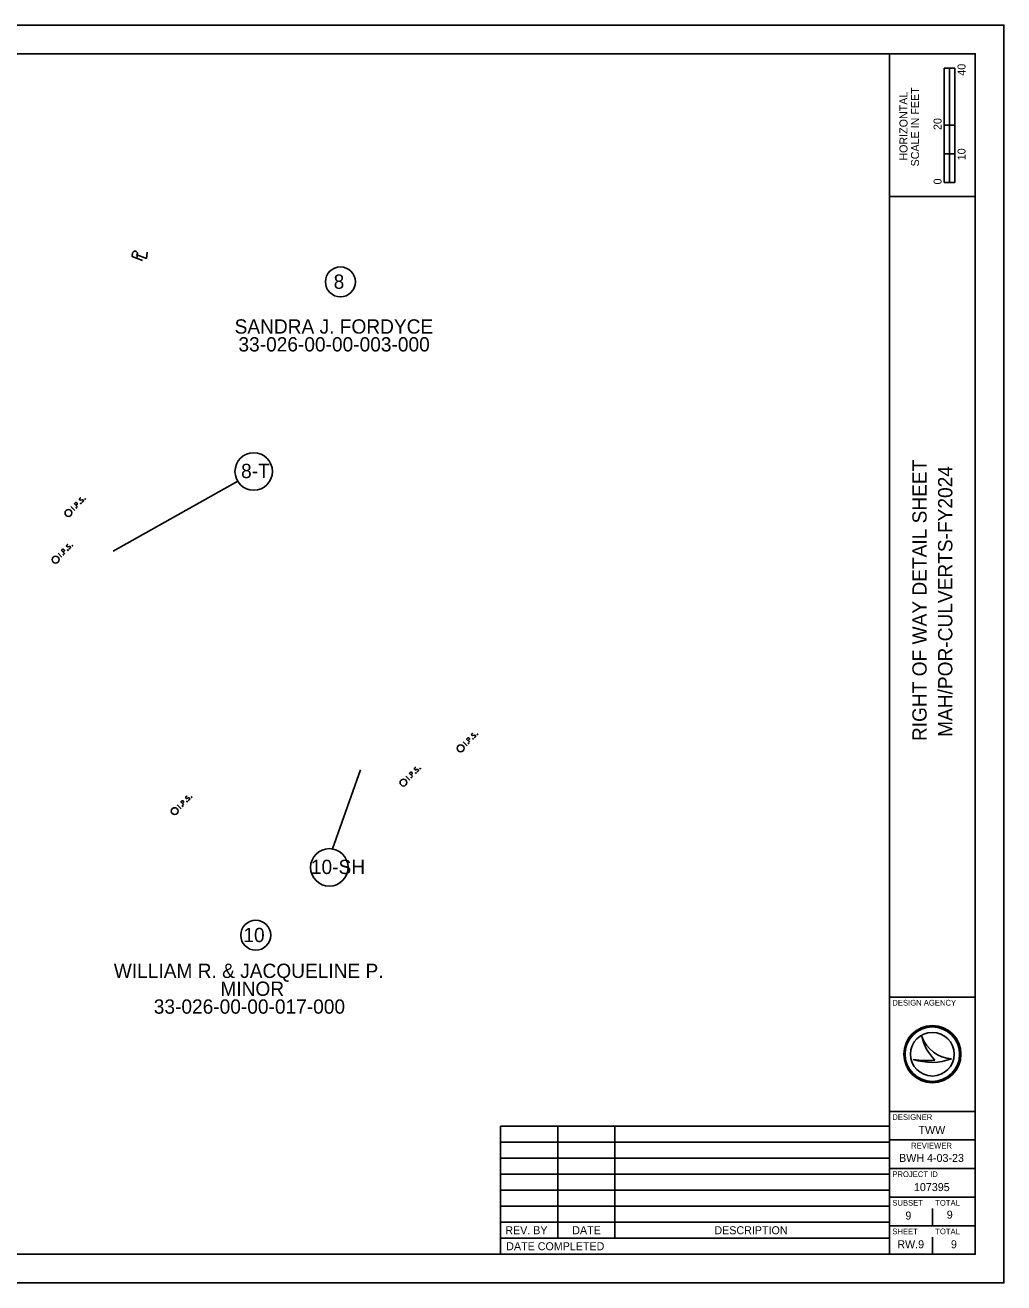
# Model space of a CAD drawing. Extents: x -0.2 to 34, y 0 to 22.
# Drawn here: x 16.88 to 34, y 0 to 22 of the extents above; entities that cross this region are included whole.
import ezdxf

# ---------------------------------------------------------------- set-up
doc = ezdxf.new("R2010")
doc.units = 0
for name, color, linetype in [('DR_X_Culvert', 7, 'Continuous'), ('DR_X_Elev_Flow', 7, 'Continuous'), ('RD_X_GR_Lt', 7, 'Continuous'), ('SH_Border', 7, 'Continuous'), ('SH_Cut_Line', 7, 'Continuous'), ('SH_Data', 7, 'Continuous'), ('SV_X_Random_Point', 7, 'Continuous'), ('UT_X_Unknown_Cells', 7, 'Continuous')]:
    doc.layers.add(name, color=color, linetype=linetype)

msp = doc.modelspace()

# ---------------------------------------------------------------- linework, layer by layer
at = {"layer": 'DR_X_Culvert'}
for p, q in [((18.839, 17.92), (18.848, 18.001)), ((18.884, 17.966), (18.884, 17.966))]:
    msp.add_line(p, q, dxfattribs=at)
for points in [[(18.935, 17.883), (18.757, 17.952), (18.764, 18.016)], [(18.826, 17.989), (19.004, 17.919), (19.016, 18.028)]]:
    msp.add_lwpolyline(points, dxfattribs=at)
msp.add_arc((18.805, 18.005), 0.0431, 354.2311, 165.0883, dxfattribs=at)
at = {"layer": 'DR_X_Elev_Flow'}
for p, q in [((20.602, 14.021), (18.422, 12.797)), ((22.261, 7.59), (22.751, 8.975)), ((25.197, 2.74), (25.197, 0.5)), ((25.197, 2.74), (32, 2.74)), ((26.197, 2.74), (26.197, 0.78)), ((27.197, 2.74), (27.197, 0.78)), ((25.197, 2.46), (32, 2.46)), ((25.197, 2.18), (32, 2.18)), ((25.197, 1.9), (32, 1.9)), ((25.197, 1.62), (32, 1.62)), ((25.197, 1.34), (32, 1.34)), ((25.197, 1.06), (32, 1.06)), ((25.197, 0.78), (32, 0.78)), ((32, 0.5), (32, 0.5))]:
    msp.add_line(p, q, dxfattribs=at)
for centre in [(20.881, 14.193), (22.203, 7.267)]:
    msp.add_circle(centre, 0.328, dxfattribs=at)
at = {"layer": 'RD_X_GR_Lt'}
for points in [[(17.802, 13.571), (17.746, 13.628), (17.764, 13.647), (17.767, 13.648), (17.77, 13.65), (17.772, 13.65), (17.774, 13.651), (17.778, 13.65), (17.782, 13.649), (17.786, 13.646), (17.791, 13.641), (17.793, 13.639), (17.795, 13.635), (17.796, 13.631), (17.796, 13.628), (17.796, 13.626), (17.795, 13.623), (17.792, 13.619), (17.773, 13.6)], [(17.856, 13.73), (17.854, 13.731), (17.852, 13.73), (17.847, 13.728), (17.842, 13.725), (17.839, 13.722), (17.838, 13.72), (17.834, 13.714), (17.833, 13.707), (17.833, 13.701), (17.836, 13.696), (17.839, 13.694), (17.843, 13.691), (17.849, 13.691), (17.884, 13.699), (17.888, 13.699), (17.891, 13.698), (17.894, 13.696), (17.897, 13.694), (17.899, 13.691), (17.9, 13.688), (17.902, 13.685), (17.903, 13.683), (17.903, 13.681), (17.904, 13.678), (17.903, 13.676), (17.903, 13.674), (17.902, 13.672), (17.899, 13.668), (17.893, 13.663), (17.889, 13.66), (17.881, 13.658), (17.875, 13.658)], [(17.93, 13.714), (17.932, 13.716), (17.934, 13.717), (17.937, 13.716), (17.939, 13.714), (17.94, 13.711), (17.939, 13.709), (17.937, 13.707), (17.935, 13.706), (17.932, 13.707), (17.93, 13.709), (17.93, 13.712), (17.93, 13.714)], [(17.684, 13.566), (17.696, 13.579)], [(17.747, 13.516), (17.69, 13.573)], [(17.741, 13.51), (17.753, 13.522)], [(17.773, 13.558), (17.775, 13.56), (17.777, 13.56), (17.78, 13.559), (17.782, 13.557), (17.783, 13.554), (17.783, 13.552), (17.781, 13.55), (17.779, 13.55), (17.776, 13.55), (17.774, 13.553), (17.773, 13.556), (17.773, 13.558)], [(17.853, 13.637), (17.855, 13.639), (17.857, 13.639), (17.86, 13.639), (17.862, 13.637), (17.862, 13.634), (17.862, 13.632), (17.86, 13.63), (17.858, 13.629), (17.855, 13.63), (17.853, 13.632), (17.852, 13.635), (17.853, 13.637)], [(17.459, 12.75), (17.471, 12.763)], [(17.577, 12.755), (17.52, 12.812), (17.539, 12.831), (17.541, 12.832), (17.545, 12.834), (17.547, 12.834), (17.549, 12.835), (17.553, 12.834), (17.556, 12.833), (17.561, 12.83), (17.566, 12.825), (17.567, 12.823), (17.569, 12.819), (17.571, 12.814), (17.571, 12.812), (17.57, 12.809), (17.569, 12.807), (17.567, 12.803), (17.548, 12.784)], [(17.631, 12.914), (17.629, 12.914), (17.627, 12.914), (17.622, 12.912), (17.617, 12.909), (17.614, 12.906), (17.613, 12.904), (17.609, 12.898), (17.607, 12.891), (17.608, 12.885), (17.611, 12.88), (17.614, 12.878), (17.618, 12.875), (17.624, 12.875), (17.659, 12.883), (17.663, 12.883), (17.665, 12.882), (17.669, 12.88), (17.671, 12.878), (17.674, 12.875), (17.675, 12.872), (17.676, 12.869), (17.677, 12.867), (17.678, 12.865), (17.678, 12.862), (17.678, 12.86), (17.677, 12.858), (17.676, 12.856), (17.673, 12.852), (17.668, 12.847), (17.664, 12.844), (17.655, 12.842), (17.65, 12.842)], [(17.627, 12.821), (17.629, 12.823), (17.631, 12.823), (17.634, 12.823), (17.636, 12.82), (17.637, 12.817), (17.637, 12.815), (17.635, 12.813), (17.633, 12.813), (17.63, 12.814), (17.628, 12.816), (17.627, 12.819), (17.627, 12.821)], [(17.704, 12.898), (17.706, 12.9), (17.708, 12.9), (17.711, 12.9), (17.714, 12.898), (17.714, 12.895), (17.714, 12.893), (17.712, 12.891), (17.71, 12.89), (17.707, 12.891), (17.705, 12.893), (17.704, 12.896), (17.704, 12.898)], [(17.521, 12.7), (17.465, 12.757)], [(17.515, 12.694), (17.528, 12.706)], [(17.548, 12.742), (17.55, 12.743), (17.552, 12.744), (17.555, 12.743), (17.557, 12.741), (17.558, 12.738), (17.557, 12.736), (17.555, 12.734), (17.553, 12.734), (17.55, 12.734), (17.548, 12.737), (17.547, 12.739), (17.548, 12.742)], [(24.543, 9.45), (24.555, 9.463)], [(24.661, 9.455), (24.605, 9.512), (24.623, 9.531), (24.626, 9.532), (24.629, 9.534), (24.631, 9.534), (24.633, 9.535), (24.637, 9.534), (24.641, 9.533), (24.645, 9.53), (24.65, 9.525), (24.652, 9.523), (24.654, 9.519), (24.655, 9.514), (24.655, 9.511), (24.655, 9.509), (24.654, 9.507), (24.651, 9.503), (24.632, 9.484)], [(24.715, 9.614), (24.713, 9.614), (24.711, 9.614), (24.706, 9.612), (24.701, 9.609), (24.698, 9.605), (24.697, 9.604), (24.693, 9.598), (24.692, 9.591), (24.692, 9.585), (24.695, 9.58), (24.698, 9.578), (24.702, 9.575), (24.708, 9.575), (24.743, 9.583), (24.747, 9.583), (24.75, 9.582), (24.753, 9.58), (24.756, 9.578), (24.758, 9.574), (24.759, 9.572), (24.761, 9.569), (24.762, 9.567), (24.762, 9.565), (24.763, 9.562), (24.762, 9.56), (24.762, 9.558), (24.761, 9.556), (24.758, 9.552), (24.752, 9.547), (24.748, 9.544), (24.74, 9.542), (24.734, 9.542)], [(24.712, 9.521), (24.714, 9.523), (24.716, 9.523), (24.719, 9.523), (24.721, 9.52), (24.721, 9.517), (24.721, 9.515), (24.719, 9.513), (24.717, 9.513), (24.714, 9.514), (24.712, 9.516), (24.711, 9.519), (24.712, 9.521)], [(24.789, 9.598), (24.791, 9.6), (24.793, 9.6), (24.796, 9.6), (24.798, 9.598), (24.799, 9.595), (24.798, 9.593), (24.796, 9.591), (24.794, 9.59), (24.791, 9.591), (24.789, 9.593), (24.789, 9.596), (24.789, 9.598)], [(24.606, 9.4), (24.549, 9.457)], [(24.6, 9.394), (24.612, 9.406)], [(24.632, 9.442), (24.634, 9.443), (24.636, 9.444), (24.639, 9.443), (24.641, 9.441), (24.642, 9.438), (24.642, 9.436), (24.64, 9.434), (24.638, 9.434), (24.635, 9.434), (24.633, 9.437), (24.632, 9.439), (24.632, 9.442)], [(23.543, 8.85), (23.555, 8.863)], [(23.606, 8.8), (23.549, 8.857)], [(23.6, 8.794), (23.612, 8.806)], [(23.661, 8.855), (23.605, 8.912), (23.623, 8.931), (23.626, 8.932), (23.629, 8.934), (23.631, 8.934), (23.633, 8.935), (23.637, 8.934), (23.641, 8.933), (23.645, 8.93), (23.65, 8.925), (23.652, 8.923), (23.654, 8.919), (23.655, 8.914), (23.655, 8.911), (23.655, 8.909), (23.654, 8.907), (23.651, 8.903), (23.632, 8.884)], [(23.632, 8.842), (23.634, 8.843), (23.636, 8.844), (23.639, 8.843), (23.641, 8.841), (23.642, 8.838), (23.642, 8.836), (23.64, 8.834), (23.638, 8.834), (23.635, 8.834), (23.632, 8.837), (23.632, 8.839), (23.632, 8.842)], [(23.715, 9.014), (23.713, 9.014), (23.711, 9.014), (23.706, 9.012), (23.701, 9.009), (23.698, 9.005), (23.697, 9.004), (23.693, 8.998), (23.692, 8.991), (23.692, 8.985), (23.695, 8.98), (23.698, 8.978), (23.702, 8.975), (23.708, 8.975), (23.743, 8.983), (23.747, 8.983), (23.75, 8.982), (23.753, 8.98), (23.756, 8.978), (23.758, 8.974), (23.759, 8.972), (23.761, 8.969), (23.762, 8.967), (23.762, 8.965), (23.763, 8.962), (23.762, 8.96), (23.762, 8.958), (23.761, 8.956), (23.758, 8.952), (23.752, 8.947), (23.748, 8.944), (23.74, 8.942), (23.734, 8.942)], [(23.712, 8.921), (23.714, 8.923), (23.716, 8.923), (23.719, 8.923), (23.721, 8.92), (23.721, 8.917), (23.721, 8.915), (23.719, 8.913), (23.717, 8.913), (23.714, 8.914), (23.712, 8.916), (23.711, 8.919), (23.712, 8.921)], [(23.789, 8.998), (23.791, 9), (23.793, 9), (23.796, 9), (23.798, 8.998), (23.799, 8.995), (23.798, 8.993), (23.796, 8.991), (23.794, 8.99), (23.791, 8.991), (23.789, 8.993), (23.789, 8.996), (23.789, 8.998)], [(19.543, 8.351), (19.555, 8.363)], [(19.661, 8.356), (19.605, 8.412), (19.623, 8.431), (19.626, 8.432), (19.629, 8.434), (19.631, 8.434), (19.633, 8.435), (19.637, 8.434), (19.641, 8.433), (19.645, 8.43), (19.65, 8.425), (19.652, 8.423), (19.654, 8.419), (19.655, 8.415), (19.655, 8.412), (19.655, 8.41), (19.654, 8.407), (19.651, 8.403), (19.632, 8.385)], [(19.715, 8.515), (19.713, 8.515), (19.711, 8.514), (19.706, 8.512), (19.701, 8.509), (19.698, 8.506), (19.697, 8.505), (19.693, 8.498), (19.692, 8.491), (19.692, 8.485), (19.695, 8.481), (19.698, 8.478), (19.702, 8.475), (19.708, 8.475), (19.743, 8.483), (19.747, 8.483), (19.75, 8.482), (19.753, 8.48), (19.756, 8.478), (19.758, 8.475), (19.759, 8.473), (19.761, 8.469), (19.762, 8.467), (19.762, 8.465), (19.763, 8.462), (19.762, 8.46), (19.762, 8.458), (19.761, 8.456), (19.758, 8.452), (19.752, 8.447), (19.748, 8.444), (19.74, 8.442), (19.734, 8.442)], [(19.712, 8.421), (19.714, 8.423), (19.716, 8.423), (19.719, 8.423), (19.721, 8.421), (19.721, 8.418), (19.721, 8.416), (19.719, 8.414), (19.717, 8.413), (19.714, 8.414), (19.712, 8.416), (19.711, 8.419), (19.712, 8.421)], [(19.789, 8.498), (19.791, 8.5), (19.793, 8.501), (19.796, 8.5), (19.798, 8.498), (19.799, 8.495), (19.798, 8.493), (19.796, 8.491), (19.794, 8.491), (19.791, 8.491), (19.789, 8.493), (19.789, 8.496), (19.789, 8.498)], [(19.606, 8.3), (19.549, 8.357)], [(19.6, 8.294), (19.612, 8.306)], [(19.632, 8.342), (19.634, 8.344), (19.636, 8.344), (19.639, 8.343), (19.641, 8.341), (19.642, 8.338), (19.642, 8.336), (19.64, 8.334), (19.638, 8.334), (19.635, 8.334), (19.632, 8.337), (19.632, 8.34), (19.632, 8.342)]]:
    msp.add_lwpolyline(points, dxfattribs=at)
for centre in [(17.641, 13.467), (17.416, 12.651), (24.5, 9.351), (23.5, 8.751), (19.5, 8.251)]:
    msp.add_circle(centre, 0.06, dxfattribs=at)
at = {"layer": 'SH_Border'}
for p, q in [((32, 0.5), (32, 21.5)), ((32, 19), (33.5, 19)), ((32, 5), (33.5, 5)), ((32, 3), (33.5, 3)), ((32, 2.5), (33.5, 2.5)), ((32, 2), (33.5, 2)), ((32, 1.5), (33.5, 1.5)), ((32, 1), (33.5, 1))]:
    msp.add_line(p, q, dxfattribs=at)
msp.add_lwpolyline([(1.5, 21.5), (33.5, 21.5), (33.5, 0.5), (1.5, 0.5)], close=True, dxfattribs=at)
at = {"layer": 'SH_Cut_Line'}
msp.add_lwpolyline([(0, 0), (34, 0), (34, 22), (0, 22)], close=True, dxfattribs=at)
at = {"layer": 'SH_Data'}
for p, q in [((32.957, 19.25), (32.957, 21.25)), ((33.144, 21.25), (32.957, 21.25)), ((32.957, 20.25), (32.957, 21.25)), ((32.957, 21.25), (33.05, 21.25)), ((33.05, 21.25), (33.051, 21.25)), ((33.051, 21.25), (33.051, 20.25)), ((33.144, 21.25), (33.144, 19.25)), ((33.051, 20.25), (32.957, 20.25)), ((33.143, 20.25), (33.05, 20.25)), ((33.05, 20.25), (33.05, 19.75)), ((33.143, 19.75), (33.143, 20.25)), ((33.05, 19.75), (32.957, 19.75)), ((32.957, 19.75), (32.957, 19.25)), ((33.05, 19.25), (33.05, 19.75)), ((33.05, 19.75), (33.143, 19.75)), ((33.144, 19.25), (32.957, 19.25)), ((32.957, 19.25), (33.05, 19.25)), ((32.567, 4.31), (32.567, 4.31)), ((32.75, 4), (32.75, 4)), ((32.417, 3.91), (32.417, 3.91)), ((33.087, 3.919), (33.087, 3.919)), ((32.75, 1), (32.75, 1.3)), ((32.375, 0.675), (32.375, 0.675)), ((32.75, 0.5), (32.75, 0.8))]:
    msp.add_line(p, q, dxfattribs=at)
for radius in [0.5, 0.477, 0.477, 0.382]:
    msp.add_circle((32.75, 4), radius, dxfattribs=at)
for centre, radius, start, end in [((33.116, 4.498), 0.58, 198.9257, 198.9319), ((33.347, 4.47), 0.796, 191.6379, 191.6421), ((33.116, 4.498), 0.58, 198.9319, 267.1657), ((33.347, 4.47), 0.796, 191.6421, 226.0947), ((32.739, 4.87), 1.013, 251.4576, 290.0832), ((32.648, 5.154), 1.266, 259.4964, 259.4995), ((32.739, 4.87), 1.013, 251.4527, 251.4576), ((32.648, 5.154), 1.266, 259.4995, 276.6672)]:
    msp.add_arc(centre, radius, start, end, dxfattribs=at)
at = {"layer": 'UT_X_Unknown_Cells'}
for centre in [(22.397, 17.509), (20.916, 6.081)]:
    msp.add_circle(centre, 0.262, dxfattribs=at)

# ---------------------------------------------------------------- texts
at = {"layer": 'DR_X_Elev_Flow'}
for s, p in [('8-T', (20.66, 14.077)), ('10-SH', (21.881, 7.151))]:
    msp.add_text(s, height=0.25, dxfattribs=at).set_placement(p)
for s, p in [('REV. BY', (25.281, 0.85)), ('DATE', (26.452, 0.85)), ('DESCRIPTION', (28.938, 0.85)), ('DATE COMPLETED', (25.297, 0.57))]:
    msp.add_text(s, height=0.14, rotation=360, dxfattribs=at).set_placement(p)
at = {"layer": 'SH_Data'}
for s, height, p in [('40', 0.14, (33.33, 21.116)), ('SCALE IN FEET', 0.14, (32.517, 19.529)), ('HORIZONTAL', 0.14, (32.315, 19.63)), ('20', 0.14, (32.911, 20.166)), ('10', 0.14, (33.33, 19.637)), ('0', 0.14, (32.911, 19.214)), ('RIGHT OF WAY DETAIL SHEET', 0.25, (32.65, 9.477)), ('MAH/POR-CULVERTS-FY2024', 0.25, (33.1, 9.55))]:
    msp.add_text(s, height=height, rotation=90, dxfattribs=at).set_placement(p)
for s, height, p in [('DESIGN AGENCY', 0.1, (32.05, 4.85)), ('DESIGNER', 0.1, (32.05, 2.85)), ('TWW', 0.14, (32.507, 2.605)), ('REVIEWER', 0.1, (32.378, 2.35)), ('PROJECT ID', 0.1, (32.05, 1.85)), ('107395', 0.14, (32.428, 1.605)), ('SUBSET', 0.1, (32.05, 1.35)), ('TOTAL', 0.1, (32.8, 1.35)), ('SHEET', 0.1, (32.05, 0.85)), ('TOTAL', 0.1, (32.8, 0.85)), ('RW.9', 0.14, (32.137, 0.605)), ('9', 0.14, (33.075, 0.605))]:
    msp.add_text(s, height=height, dxfattribs=at).set_placement(p)
at = {"layer": 'SV_X_Random_Point'}
for s, p in [('BWH 4-03-23', (32.168, 2.115)), ('9', (32.278, 1.107)), ('9', (33.002, 1.123))]:
    msp.add_text(s, height=0.14, rotation=360, dxfattribs=at).set_placement(p)
at = {"layer": 'UT_X_Unknown_Cells'}
for s, p in [('8', (22.279, 17.388)), ('SANDRA J. FORDYCE', (20.547, 16.604)), ('33-026-00-00-003-000', (20.614, 16.292)), ('10', (20.7, 5.96)), ('WILLIAM R. & JACQUELINE P.', (18.434, 5.333)), ('MINOR', (20.298, 5.02)), ('33-026-00-00-017-000', (19.133, 4.708))]:
    msp.add_text(s, height=0.25, dxfattribs=at).set_placement(p)

doc.saveas('drawing.dxf')
